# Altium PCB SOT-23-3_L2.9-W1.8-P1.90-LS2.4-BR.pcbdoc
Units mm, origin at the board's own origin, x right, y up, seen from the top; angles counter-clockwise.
Board outline 15.94 x 15.71 mm, 2 copper layers (Top Layer, Bottom Layer), stack 0 mm thick; 1 components, 0 nets, 3 pads, 0 vias.
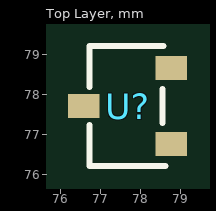
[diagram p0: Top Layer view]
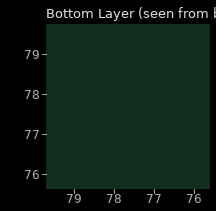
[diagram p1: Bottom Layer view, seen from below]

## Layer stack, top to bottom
Top Layer: signal copper (thickness not stored)
Bottom Layer: signal copper (thickness not stored)

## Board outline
85.785,69.85 69.85,69.85 69.85,85.56 85.785,85.56

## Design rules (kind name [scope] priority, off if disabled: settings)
PasteMaskExpansion "Paste Mask Expansion" [All] p1: expansion=0
SolderMaskExpansion "Solder Mask Expansion" [IsVia] p1: expansion=-25.4 istentingtop=TRUE
SolderMaskExpansion "Solder Mask Expansion" [All] p2: expansion=0.051 istentingtop=FALSE

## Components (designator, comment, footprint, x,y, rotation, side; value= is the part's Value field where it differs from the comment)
U? "" SOT-23-3_L2.9-W1.8-P1.90-LS2.4-BR 77.685,77.71 r0 top

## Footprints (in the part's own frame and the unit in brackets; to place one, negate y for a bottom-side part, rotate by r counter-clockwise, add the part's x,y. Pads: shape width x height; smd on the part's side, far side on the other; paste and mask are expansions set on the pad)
SOT-23-3_L2.9-W1.8-P1.90-LS2.4-BR [mm]
  rect 0.785x0.595 smd: 1(1.093,-0.95) 2(1.093,0.95) 3(-1.093,0)
  silkscreen extent -0.95,-1.5 0.95,1.5

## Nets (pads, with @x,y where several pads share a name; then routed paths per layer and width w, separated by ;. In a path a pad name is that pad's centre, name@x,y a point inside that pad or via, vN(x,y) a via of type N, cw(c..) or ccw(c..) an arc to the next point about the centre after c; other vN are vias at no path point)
pads on no net: U?.1 U?.2 U?.3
